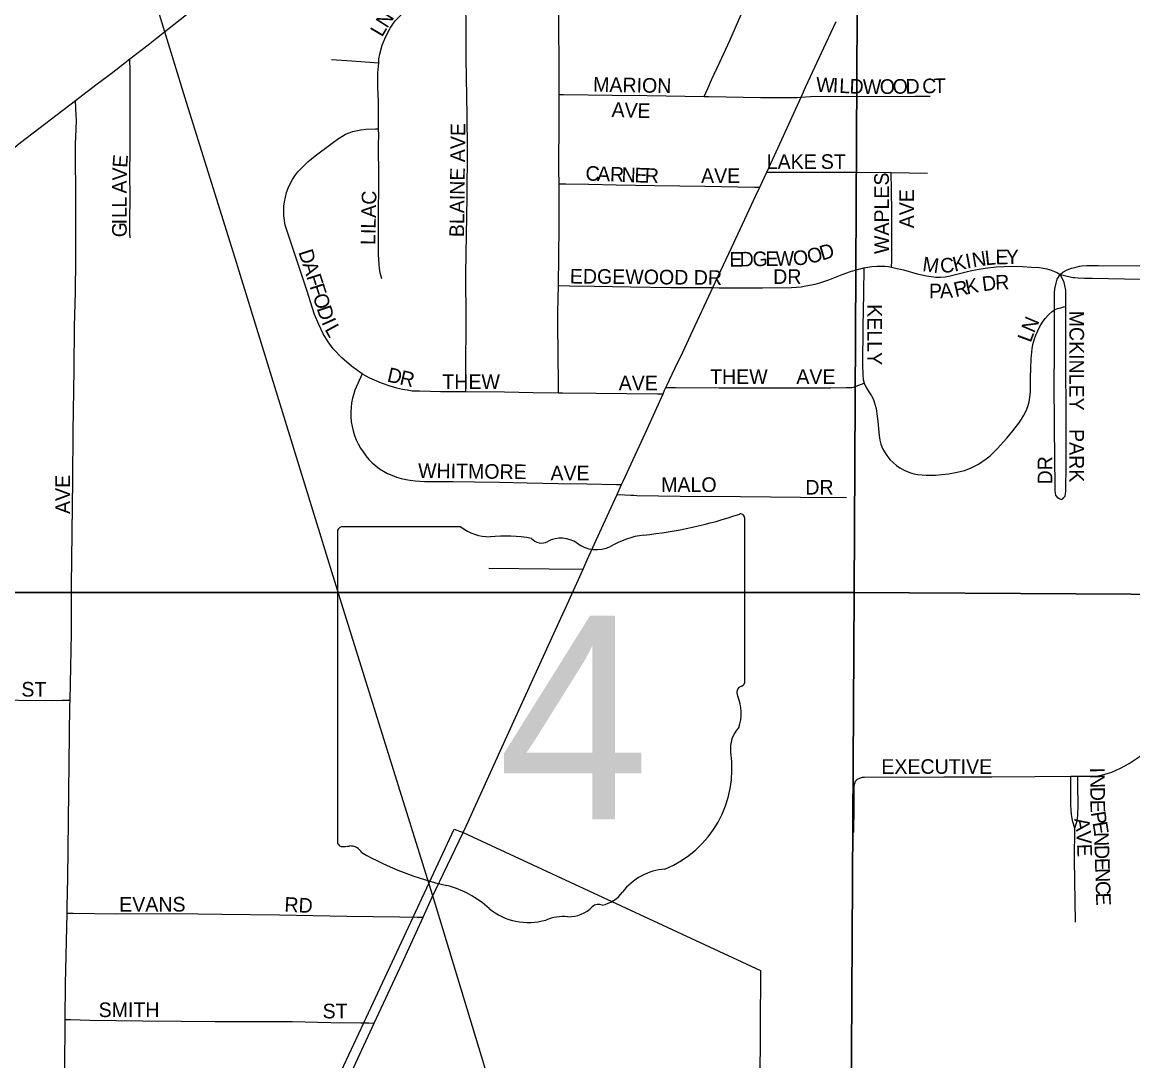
# Model space of a CAD drawing. Extents: x -9.1 to 34, y -3.1 to 22.
# Drawn here: x 4.682 to 5.401, y 18.468 to 19.14 of the extents above; entities that cross this region are included whole.
import ezdxf

# ---------------------------------------------------------------- set-up
doc = ezdxf.new("R2010")
doc.units = 0
for name, color, linetype in [('GM_X_City_Street', 7, 'Continuous'), ('GM_X_City_Street_Text', 7, 'Continuous'), ('GM_X_Corporation', 7, 'Continuous'), ('GM_X_Rail_Line', 7, 'Continuous'), ('GM_X_Section', 7, 'Continuous'), ('GM_X_State_Location', 7, 'Continuous'), ('GM_X_State_Route', 7, 'Continuous'), ('GM_X_State_Shield', 7, 'Continuous')]:
    doc.layers.add(name, color=color, linetype=linetype)

msp = doc.modelspace()

# ---------------------------------------------------------------- linework, layer by layer
at = {"layer": 'GM_X_City_Street'}
for points in [[(4.91297, 19.11392), (4.91314, 19.11648), (4.91366, 19.11945), (4.91532, 19.12531), (4.91758, 19.13096), (4.92048, 19.1363), (4.92217, 19.13882), (4.92372, 19.14106), (4.92573, 19.14333), (4.9315, 19.14874), (4.9371, 19.15333), (4.93817, 19.15402)], [(4.96929, 18.90117), (4.96949, 18.91567), (4.96959, 18.94655), (4.96942, 18.97748), (4.97034, 19.02704), (4.97051, 19.05804), (4.97028, 19.07974), (4.96967, 19.11681), (4.9697, 19.13525), (4.96932, 19.15375)], [(5.02979, 19.09342), (5.02971, 19.10364), (5.0296, 19.1469), (5.02965, 19.15302)], [(5.12373, 19.09213), (5.12599, 19.0973), (5.12848, 19.10298), (5.13376, 19.11422), (5.14028, 19.12825), (5.14764, 19.14525), (5.14855, 19.14822), (5.14927, 19.15143)], [(4.75203, 19.00066), (4.75192, 19.00372), (4.75181, 19.01296), (4.75208, 19.02528), (4.75187, 19.04376), (4.75213, 19.05609), (4.75213, 19.06533), (4.75216, 19.10541), (4.75211, 19.10848), (4.75198, 19.11642)], [(4.88235, 19.11607), (4.89564, 19.11509), (4.91, 19.11412), (4.91297, 19.11392)], [(4.91294, 19.07125), (4.91279, 19.08884), (4.91247, 19.09805), (4.91252, 19.10732), (4.91297, 19.11392)], [(4.71316, 18.70123), (4.71407, 18.74446), (4.71423, 18.77554), (4.71507, 18.8439), (4.71525, 18.87498), (4.71579, 18.91537), (4.71612, 18.94334), (4.71661, 18.96508), (4.71688, 18.98679), (4.71693, 19.02096), (4.71677, 19.06135), (4.7171, 19.07066), (4.71727, 19.07681), (4.71713, 19.07984), (4.71666, 19.08949)], [(5.02971, 19.03553), (5.02961, 19.04447), (5.02991, 19.07835), (5.02979, 19.09342)], [(5.02979, 19.09342), (5.03259, 19.09338), (5.04859, 19.09316), (5.06417, 19.09295), (5.08683, 19.09264), (5.12373, 19.09213)], [(5.12373, 19.09213), (5.12664, 19.09209), (5.16009, 19.09154), (5.17997, 19.09133), (5.18226, 19.0914), (5.18395, 19.09146), (5.18641, 19.09166)], [(5.18641, 19.09166), (5.19246, 19.09206), (5.19491, 19.09222), (5.22894, 19.09206), (5.2602, 19.09228), (5.27002, 19.09225)], [(4.90221, 18.91247), (4.89537, 18.91746), (4.88905, 18.92287), (4.88362, 18.92874), (4.88024, 18.93327), (4.87713, 18.93834), (4.87419, 18.94447), (4.87153, 18.95088), (4.8664, 18.96659), (4.86129, 18.98226), (4.85444, 19.00289), (4.85253, 19.00883), (4.85193, 19.01183), (4.85159, 19.01485), (4.85151, 19.01789), (4.85168, 19.02084), (4.85203, 19.02387), (4.85259, 19.02699), (4.8534, 19.02988), (4.85447, 19.03274), (4.85573, 19.03555), (4.85728, 19.03837), (4.85878, 19.0408), (4.86065, 19.04321), (4.8627, 19.04547), (4.86718, 19.04972), (4.87195, 19.05365), (4.8819, 19.06115), (4.88693, 19.0648), (4.88921, 19.06622), (4.89152, 19.06765), (4.89387, 19.06862), (4.89613, 19.06932), (4.90135, 19.07045), (4.90473, 19.0709), (4.91095, 19.07116), (4.91294, 19.07125)], [(4.91504, 18.97408), (4.914, 18.97798), (4.91348, 18.98085), (4.91326, 18.98351), (4.91292, 18.98976), (4.91287, 19.00522), (4.91298, 19.04547), (4.91291, 19.05475), (4.91292, 19.06093), (4.91297, 19.06712), (4.91294, 19.07125)], [(5.16425, 19.0432), (5.17026, 19.04317), (5.18413, 19.04308), (5.20057, 19.04308), (5.22188, 19.04299), (5.24474, 19.04298)], [(5.24474, 19.04298), (5.25648, 19.04267), (5.26822, 19.04245)], [(5.24498, 18.98153), (5.24511, 18.9858), (5.24511, 18.9979), (5.24511, 19.00599), (5.24511, 19.01746), (5.2449, 19.03159), (5.24474, 19.04298)], [(5.02943, 18.96969), (5.02953, 18.98878), (5.02984, 19.00734), (5.02985, 19.02275), (5.02971, 19.03553)], [(5.02971, 19.03553), (5.03403, 19.03546), (5.0488, 19.03525), (5.06675, 19.035), (5.09165, 19.03448), (5.12419, 19.03395), (5.15621, 19.03343), (5.15972, 19.03336)], [(5.12933, 18.96832), (5.13334, 18.96831), (5.16154, 18.96829), (5.18025, 18.96847), (5.18334, 18.96864), (5.18641, 18.96896), (5.18947, 18.96941), (5.19552, 18.97067), (5.1985, 18.97148), (5.20437, 18.97346), (5.2131, 18.97693), (5.21842, 18.9788), (5.22304, 18.98013), (5.22704, 18.98111)], [(5.22704, 18.98111), (5.2268, 18.96479), (5.22645, 18.94292), (5.22628, 18.91811), (5.22637, 18.91189), (5.22663, 18.9089), (5.22717, 18.90654)], [(5.22704, 18.98111), (5.23219, 18.98191), (5.23549, 18.98218), (5.23789, 18.98227), (5.24065, 18.98218), (5.24296, 18.98191), (5.24498, 18.98153)], [(5.24498, 18.98153), (5.24673, 18.98125), (5.25281, 18.97977), (5.26166, 18.97724), (5.2676, 18.97592), (5.2706, 18.97546), (5.2736, 18.97518), (5.2766, 18.9751), (5.27971, 18.97539), (5.28291, 18.97592), (5.28816, 18.97717), (5.29589, 18.97913), (5.30043, 18.98011), (5.30549, 18.98091), (5.31279, 18.98172), (5.31794, 18.98207), (5.32274, 18.98216), (5.32977, 18.98198), (5.33563, 18.98163), (5.34079, 18.98127), (5.34315, 18.98095), (5.34546, 18.98051), (5.3476, 18.97989), (5.35, 18.97909), (5.35231, 18.97802), (5.35418, 18.97686)], [(5.35418, 18.97686), (5.35595, 18.97832), (5.35861, 18.97977), (5.3615, 18.9809), (5.3636, 18.9814), (5.36521, 18.98185), (5.36672, 18.9822), (5.36814, 18.98238), (5.37134, 18.98256), (5.37881, 18.98274), (5.45205, 18.98239), (5.47362, 18.98231)], [(5.35048, 18.95403), (5.35048, 18.95741), (5.3505, 18.96545), (5.3506, 18.96725), (5.35084, 18.96834), (5.35145, 18.97116), (5.35225, 18.97382), (5.35418, 18.97686)], [(5.3578, 18.95612), (5.35775, 18.9667), (5.35767, 18.96777), (5.35744, 18.96866), (5.35675, 18.97157), (5.35571, 18.97398), (5.35418, 18.97686)], [(5.35418, 18.97686), (5.36058, 18.97527), (5.36227, 18.97491), (5.36366, 18.97481), (5.36576, 18.97467), (5.3698, 18.97452), (5.37507, 18.97438), (5.39588, 18.97412), (5.44625, 18.97379), (5.47099, 18.97364), (5.47359, 18.97362)], [(5.02933, 18.90032), (5.02929, 18.90388), (5.02908, 18.9269), (5.02894, 18.94281), (5.02904, 18.95231), (5.02943, 18.96969)], [(5.02943, 18.96969), (5.03644, 18.96959), (5.05277, 18.96928), (5.07598, 18.96893), (5.10203, 18.96841), (5.12073, 18.96835), (5.12933, 18.96832)], [(5.22717, 18.90654), (5.2286, 18.90362), (5.23037, 18.90078), (5.23206, 18.8982), (5.23305, 18.89624), (5.23375, 18.89446), (5.23438, 18.89233), (5.23492, 18.89011), (5.23554, 18.88673), (5.23599, 18.88343), (5.23625, 18.87979), (5.23652, 18.87659), (5.23687, 18.87268), (5.23741, 18.86956), (5.23812, 18.8669), (5.2391, 18.86423), (5.24035, 18.86192), (5.24186, 18.8597), (5.2439, 18.85712), (5.24621, 18.85481), (5.24808, 18.85321), (5.25039, 18.85161), (5.25351, 18.84983), (5.25716, 18.84832), (5.25955, 18.8477), (5.26195, 18.84725), (5.26747, 18.8469), (5.27342, 18.8469), (5.27752, 18.84734), (5.28178, 18.84788), (5.28747, 18.84886), (5.29228, 18.85002), (5.29619, 18.85144), (5.30125, 18.85402), (5.30632, 18.8574), (5.30888, 18.85949), (5.3133, 18.86387), (5.31955, 18.87079), (5.32354, 18.87557), (5.32728, 18.88056), (5.32901, 18.88314), (5.33061, 18.88581), (5.33204, 18.88857), (5.33319, 18.89144), (5.33405, 18.89441), (5.3346, 18.89746), (5.33489, 18.90055), (5.335, 18.90367), (5.335, 18.90989), (5.33516, 18.91611), (5.33529, 18.92232), (5.336, 18.92863), (5.33654, 18.93148), (5.33734, 18.93459), (5.33847, 18.93756), (5.33962, 18.94044), (5.34102, 18.94323), (5.34263, 18.94589), (5.34449, 18.94837), (5.34664, 18.95075), (5.34887, 18.9528), (5.35048, 18.95403)], [(5.35472, 18.8311), (5.35356, 18.8315), (5.35254, 18.83226), (5.35137, 18.83391), (5.35106, 18.83524), (5.35083, 18.83707), (5.3508, 18.84217), (5.35058, 18.85586), (5.3503, 18.90548), (5.35039, 18.92638), (5.35047, 18.94549), (5.35048, 18.95403)], [(5.35048, 18.95403), (5.35232, 18.95475), (5.35446, 18.95536), (5.35618, 18.95585), (5.3578, 18.95612)], [(5.35472, 18.8311), (5.35575, 18.8315), (5.3566, 18.83248), (5.35731, 18.83339), (5.35767, 18.83494), (5.3579, 18.83632), (5.3579, 18.83718), (5.35806, 18.85361), (5.358, 18.87103), (5.35794, 18.89139), (5.35786, 18.91415), (5.35776, 18.94519), (5.3578, 18.95612)], [(4.90221, 18.91247), (4.89759, 18.90192), (4.89682, 18.89968), (4.89605, 18.89671), (4.89546, 18.89372), (4.8951, 18.8907), (4.89496, 18.88765), (4.895, 18.88458), (4.89526, 18.88154), (4.89572, 18.87852), (4.89641, 18.87556), (4.89729, 18.87265), (4.8984, 18.86983), (4.89976, 18.86711), (4.90128, 18.86449), (4.90299, 18.86192), (4.90475, 18.85942), (4.90668, 18.85711), (4.90882, 18.85491), (4.91109, 18.85289), (4.91352, 18.85107), (4.91609, 18.84944), (4.91879, 18.84803), (4.92159, 18.84682), (4.92446, 18.84572), (4.92748, 18.84483), (4.93184, 18.84386), (4.93655, 18.84324), (4.94259, 18.84288), (4.961, 18.84274), (4.97505, 18.8426), (4.99123, 18.84236), (5.0091, 18.842), (5.02917, 18.8416), (5.0477, 18.8414), (5.06699, 18.84086), (5.07017, 18.84078)], [(4.90221, 18.91247), (4.9071, 18.90998), (4.91457, 18.90678), (4.92026, 18.90474), (4.92462, 18.9035), (4.92844, 18.90259), (4.93141, 18.90211), (4.93462, 18.90162), (4.93936, 18.90147)], [(4.93936, 18.90147), (4.95302, 18.90119), (4.96292, 18.90113), (4.96929, 18.90117)], [(4.96929, 18.90117), (4.99437, 18.90085), (5.01293, 18.9005), (5.02933, 18.90032)], [(5.0989, 18.90367), (5.10516, 18.90363), (5.13335, 18.90347), (5.16509, 18.90341), (5.18536, 18.90337), (5.20559, 18.90344), (5.21568, 18.90357), (5.21746, 18.90357), (5.21933, 18.90375), (5.2211, 18.90419), (5.22386, 18.90526), (5.22717, 18.90654)], [(5.02933, 18.90032), (5.03206, 18.90029), (5.05385, 18.90006), (5.0935, 18.89963), (5.09707, 18.89959)], [(5.06733, 18.83445), (5.07224, 18.83421), (5.07619, 18.83402), (5.07816, 18.83392), (5.08003, 18.83383), (5.10804, 18.83339), (5.14725, 18.83305), (5.18593, 18.83271), (5.2158, 18.83244)], [(4.98424, 18.78675), (5.02342, 18.78624), (5.04537, 18.78615)], [(4.57609, 18.70589), (4.5791, 18.70553), (4.58614, 18.70468), (4.59201, 18.70398), (4.60136, 18.70304), (4.61387, 18.70216), (4.62504, 18.70178), (4.63584, 18.70173), (4.70177, 18.70105), (4.70805, 18.70115), (4.71316, 18.70123)], [(4.71123, 18.56338), (4.71133, 18.56737), (4.71167, 18.586), (4.71229, 18.62328), (4.71309, 18.69787), (4.71316, 18.70123)], [(5.36551, 18.65202), (5.3754, 18.65206), (5.3785, 18.65233), (5.38156, 18.65289), (5.38458, 18.65366), (5.38752, 18.65465), (5.3904, 18.65581), (5.39322, 18.65712), (5.3987, 18.66014), (5.40396, 18.66358), (5.41163, 18.66903), (5.41433, 18.67056), (5.41989, 18.67327), (5.42878, 18.67618), (5.44959, 18.68281), (5.4644, 18.68766), (5.48212, 18.69348), (5.49345, 18.6971)], [(5.22063, 18.61561), (5.22067, 18.63188), (5.22071, 18.64565), (5.22114, 18.64723), (5.22174, 18.64875), (5.22304, 18.65016)], [(5.22304, 18.65016), (5.22483, 18.65102), (5.22618, 18.6514), (5.22748, 18.65144), (5.27873, 18.6517), (5.30993, 18.65168), (5.33768, 18.65189), (5.36114, 18.65199)], [(5.36356, 18.61844), (5.36238, 18.62238), (5.36198, 18.62455), (5.36154, 18.62723), (5.36124, 18.63), (5.36104, 18.63354), (5.36112, 18.64726), (5.36114, 18.65199)], [(5.36114, 18.65199), (5.36551, 18.65202)], [(5.36356, 18.61844), (5.36484, 18.62248), (5.36534, 18.62465), (5.36562, 18.62688), (5.36581, 18.63321), (5.36561, 18.64589), (5.36551, 18.65202)], [(5.36397, 18.55746), (5.36347, 18.59803), (5.36356, 18.61844)], [(4.70999, 18.49453), (4.71016, 18.51765), (4.71123, 18.56338)], [(4.71123, 18.56338), (4.71512, 18.56333), (4.74308, 18.56294), (4.7804, 18.56306), (4.81149, 18.56263), (4.84882, 18.56228), (4.89233, 18.56128), (4.92654, 18.56091), (4.9378, 18.56083), (4.94177, 18.56081)], [(4.70955, 18.4257), (4.70964, 18.43064), (4.70974, 18.46172), (4.70999, 18.49453)], [(4.70999, 18.49453), (4.71352, 18.49444), (4.72598, 18.49413), (4.76001, 18.49372), (4.78521, 18.49337), (4.80706, 18.49322), (4.83828, 18.49313), (4.85701, 18.49308), (4.88197, 18.49264), (4.90132, 18.49239), (4.90662, 18.49226), (4.91007, 18.49218)]]:
    msp.add_lwpolyline(points, dxfattribs=at)
at = {"layer": 'GM_X_Corporation'}
msp.add_lwpolyline([(4.48709, 18.28022), (4.70754, 18.2776), (4.80082, 18.27528), (4.82, 18.31687), (4.83638, 18.35097), (4.87109, 18.42324), (4.90339, 18.49229), (4.93534, 18.5608), (4.96194, 18.61779), (4.96775, 18.61559), (5.16013, 18.52629), (5.15861, 18.26589), (5.2044, 18.26599), (5.22711, 18.26576), (5.2741, 18.26585), (5.53122, 18.26459)], dxfattribs=at)
at = {"layer": 'GM_X_Rail_Line'}
msp.add_lwpolyline([(5.35605, 17.26065), (5.18547, 17.8126), (5.12815, 17.99868), (5.11158, 18.04263), (5.04323, 18.26559), (4.98762, 18.44451), (4.9489, 18.57172), (4.88796, 18.76688), (4.82092, 18.98452), (4.78778, 19.09094), (4.76193, 19.17487)], dxfattribs=at)
at = {"layer": 'GM_X_Section'}
for points in [[(4.2285, 19.77719), (5.226, 19.77229), (5.22068, 18.771), (4.22542, 18.77097)], [(5.226, 19.77229), (6.2379, 19.76083), (6.22532, 18.76489), (5.22068, 18.771)], [(4.22542, 18.77097), (5.22068, 18.771), (5.21493, 17.76405), (4.21254, 17.77165)], [(5.22068, 18.771), (6.22532, 18.76489), (6.22405, 17.76169), (5.21493, 17.76405)]]:
    msp.add_lwpolyline(points, close=True, dxfattribs=at)
at = {"layer": 'GM_X_State_Route'}
for points in [[(4.76383, 19.12561), (4.76922, 19.12978), (4.79575, 19.15075)], [(5.03384, 18.76073), (5.04537, 18.78615), (5.04803, 18.79206), (5.06098, 18.8203), (5.06733, 18.83445), (5.07017, 18.84078), (5.07115, 18.84299), (5.08036, 18.86262), (5.08687, 18.87675), (5.09303, 18.89057), (5.09707, 18.89959), (5.09808, 18.90185), (5.0989, 18.90367), (5.09948, 18.90491), (5.10468, 18.91605), (5.10977, 18.92665), (5.11637, 18.94062), (5.12825, 18.96599), (5.12933, 18.96832), (5.1414, 18.99416), (5.15722, 19.02794), (5.15972, 19.03336), (5.16425, 19.0432), (5.17151, 19.05898), (5.18641, 19.09166), (5.18954, 19.0986), (5.20259, 19.12673), (5.20908, 19.14056)], [(4.61624, 19.01095), (4.66437, 19.04881), (4.68111, 19.06222), (4.71666, 19.08949), (4.72979, 19.09956), (4.73975, 19.10696), (4.75198, 19.11642), (4.76383, 19.12561)], [(4.96775, 18.61559), (4.9696, 18.61966), (4.9937, 18.67303), (5.01163, 18.71226), (5.0309, 18.75426), (5.03384, 18.76073)], [(4.87767, 18.42312), (4.88518, 18.43842), (4.89813, 18.46653), (4.91007, 18.49218), (4.92815, 18.53102), (4.94177, 18.56081), (4.94745, 18.5732), (4.96775, 18.61559)]]:
    msp.add_lwpolyline(points, dxfattribs=at)
at = {"layer": 'GM_X_State_Shield'}
for p, q in [((5.15001, 18.71374), (5.15001, 18.81842)), ((4.88634, 18.81002), (4.88634, 18.6099)), ((4.96615, 18.81346), (4.88894, 18.81346)), ((5.14998, 18.71376), (5.15001, 18.71374))]:
    msp.add_line(p, q, dxfattribs=at)
for centre, radius, start, end in [((5.05609, 19.08629), 0.27962, 275.84447, 288.90645), ((5.14708, 18.81886), 0.00294, 351.86209, 97.738), ((4.88936, 18.81044), 0.00305, 98.1301, 188.1301), ((4.98454, 18.83669), 0.02963, 231.61951, 271.11188), ((4.99437, 18.70111), 0.10636, 80.48669, 94.98827), ((5.09175, 18.75234), 0.05625, 97.34618, 120.76885), ((5.01851, 18.81148), 0.00855, 219.79206, 297.10237), ((5.03106, 18.78835), 0.01777, 54.46668, 119.14113), ((5.054, 18.82008), 0.02138, 233.85621, 294.82819), ((5.14688, 18.71333), 0.00314, 289.60381, 7.73413), ((5.14933, 18.70605), 0.00454, 107.94398, 210.33697), ((5.12043, 18.69282), 0.02727, 340.03296, 23.64957), ((5.16052, 18.66993), 0.01984, 136.8065, 186.92959), ((5.07175, 18.65661), 0.06994, 292.30889, 8.98584), ((4.88939, 18.60946), 0.00308, 171.95839, 258.30661), ((4.88986, 18.62993), 0.02352, 267.33899, 280.60386), ((4.89467, 18.59835), 0.00848, 29.74838, 93.27175), ((5.00173, 18.77815), 0.20192, 240.41292, 257.1985), ((5.10124, 18.55371), 0.0383, 94.40312, 142.57675), ((4.94153, 18.51999), 0.06318, 47.18416, 75.83597), ((5.05271, 18.5905), 0.0226, 282.87319, 323.27711), ((5.00986, 18.59736), 0.04009, 230.70037, 286.29184), ((5.03595, 18.58237), 0.02136, 268.77702, 315.54927), ((5.05527, 18.56299), 0.00601, 65.75173, 132.64842), ((5.03302, 18.52817), 0.03294, 85.69512, 111.20995)]:
    msp.add_arc(centre, radius, start, end, dxfattribs=at)

# ---------------------------------------------------------------- texts
at = {"layer": 'GM_X_City_Street_Text'}
for s, height, rotation, p in [('N', 0.00947, 57.35276, (4.91845, 19.13577)), ('L', 0.00947, 59.48597, (4.91512, 19.13011)), ('MARION', 0.00947, 358.97529, (5.05173, 19.09521)), ('W', 0.00947, 357.17453, (5.19593, 19.0952)), ('I', 0.00947, 357.15724, (5.20675, 19.09467)), ('L', 0.00947, 357.15085, (5.21091, 19.09446)), ('D', 0.00947, 357.18919, (5.21758, 19.09413)), ('W', 0.00947, 359.7945, (5.22637, 19.09371)), ('O', 0.00947, 0.90537, (5.23741, 19.09368)), ('O', 0.00947, 0.92786, (5.24574, 19.09381)), ('D', 0.00947, 0.93858, (5.25407, 19.09394)), ('C', 0.00947, 0.92287, (5.26492, 19.09412)), ('T', 0.00947, 0.93643, (5.27242, 19.09424)), ('A', 0.00947, 357.87971, (5.06364, 19.07892)), ('V', 0.00947, 357.9211, (5.07198, 19.07862)), ('E', 0.00947, 358.29811, (5.08037, 19.07831)), ('BLAINE AVE', 0.00947, 89.30946, (4.96823, 19.00096)), ('E', 0.00947, 85.98055, (4.75012, 19.04575)), ('LAKE', 0.00947, 0.00001, (5.16418, 19.0452)), ('ST', 0.00947, 0.00001, (5.19918, 19.0452)), ('V', 0.00947, 88.57936, (4.74992, 19.03753)), ('C', 0.00947, 357.91126, (5.04675, 19.0377)), ('A', 0.00947, 357.90155, (5.05424, 19.03743)), ('R', 0.00947, 357.91472, (5.06257, 19.03713)), ('N', 0.00947, 357.9211, (5.07007, 19.03685)), ('E', 0.00947, 357.89609, (5.0784, 19.03655)), ('R', 0.00947, 358.24792, (5.08512, 19.0363)), ('AVE', 0.00947, 0.00001, (5.12168, 19.03604)), ('A', 0.00947, 89.95627, (4.74991, 19.02926)), ('WAPLES', 0.00947, 90, (5.24323, 18.99009)), ('LILAC', 0.00947, 88.63187, (4.91073, 18.99586)), ('AVE', 0.00947, 90, (5.25952, 19.00676)), ('L', 0.00947, 89.97066, (4.74991, 19.02009)), ('L', 0.00947, 89.97066, (4.7499, 19.01343)), ('G', 0.00947, 89.97813, (4.7499, 19.00092)), ('I', 0.00947, 89.95628, (4.7499, 19.00925)), ('O', 0.00947, 15.04495, (5.1917, 18.98358)), ('D', 0.00947, 16.56864, (5.20001, 18.98582)), ('D', 0.00947, 288.02028, (4.8609, 18.99138)), ('E', 0.00947, 0.98352, (5.14006, 18.98187)), ('D', 0.00947, 0.98362, (5.14672, 18.98199)), ('G', 0.00947, 0.98362, (5.15505, 18.98213)), ('E', 0.00947, 1.01138, (5.16339, 18.98228)), ('W', 0.00947, 0.9753, (5.17005, 18.98239)), ('O', 0.00947, 4.46346, (5.18151, 18.98261)), ('M', 0.00947, 352.23566, (5.2646, 18.97909)), ('C', 0.00947, 5.38814, (5.27688, 18.97769)), ('K', 0.00947, 13.78316, (5.28583, 18.97864)), ('I', 0.00947, 10.82112, (5.2938, 18.9806)), ('N', 0.00947, 9.28625, (5.29782, 18.98137)), ('L', 0.00947, 6.132, (5.30591, 18.9827)), ('E', 0.00947, 1.03815, (5.31232, 18.9834)), ('Y', 0.00947, 0.13116, (5.31894, 18.98352)), ('A', 0.00947, 288.02106, (4.86348, 18.98346)), ('EDGEWOOD DR', 0.0094697, 359.44379, (5.0367, 18.97104)), ('DR', 0.00947, 0.00001, (5.16835, 18.97076)), ('F', 0.00947, 288.02073, (4.86606, 18.97553)), ('R', 0.00947, 13.01676, (5.28647, 18.9622)), ('K', 0.00947, 11.41707, (5.29371, 18.96387)), ('D', 0.00947, 7.60764, (5.30418, 18.96592)), ('R', 0.00947, 1.77322, (5.31219, 18.967)), ('F', 0.00947, 288.02073, (4.86812, 18.96919)), ('P', 0.00947, 0.10929, (5.26918, 18.96141)), ('A', 0.00947, 3.47872, (5.27646, 18.96144)), ('O', 0.00947, 288.02106, (4.87018, 18.96285)), ('D', 0.00947, 288.03547, (4.87276, 18.95493)), ('KELLY', 0.00947, 270, (5.22926, 18.95759)), ('MCKINLEY', 0.00947, 270, (5.36012, 18.95342)), ('I', 0.00947, 294.23788, (4.87575, 18.94596)), ('L', 0.00947, 298.67549, (4.87782, 18.94144)), ('N', 0.00947, 66.98506, (5.33731, 18.93845)), ('L', 0.00947, 69.54307, (5.33502, 18.93231)), ('D', 0.00947, 347.10369, (4.91794, 18.90765)), ('R', 0.00947, 347.08789, (4.92606, 18.90579)), ('THEW', 0.00947, 0.00001, (5.12751, 18.90604)), ('AVE', 0.00947, 0.00001, (5.18334, 18.90604)), ('THEW', 0.00947, 0.00001, (4.95418, 18.9027)), ('AVE', 0.00947, 0.00001, (5.06834, 18.90187)), ('PARK', 0.00947, 270, (5.36012, 18.87676)), ('DR', 0.00947, 90, (5.34907, 18.84092)), ('WHITMORE', 0.00947, 359.2713, (4.93841, 18.84521)), ('AVE', 0.00947, 0.00001, (5.02418, 18.84354)), ('AVE', 0.00947, 90, (4.71323, 18.82176)), ('MALO', 0.00947, 0.00001, (5.09584, 18.83604)), ('DR', 0.00947, 0.00001, (5.18918, 18.83437)), ('ST', 0.00947, 0.00001, (4.68168, 18.70354)), ('EXECUTIVE', 0.00947, 0.00001, (5.23835, 18.65354)), ('I', 0.00947, 270.69923, (5.37346, 18.65756)), ('N', 0.00947, 270.67764, (5.37351, 18.65339)), ('D', 0.00947, 270.69119, (5.37361, 18.64506)), ('E', 0.00947, 270.68304, (5.37371, 18.63672)), ('P', 0.00947, 279.43041, (5.37393, 18.62849)), ('A', 0.00947, 278.99877, (5.36326, 18.6243)), ('E', 0.00947, 279.33205, (5.37502, 18.62191)), ('V', 0.00947, 273.71813, (5.36454, 18.6163)), ('N', 0.00947, 271.7708, (5.37607, 18.61566)), ('E', 0.00947, 272.35068, (5.36507, 18.60804)), ('D', 0.00947, 271.74896, (5.37633, 18.60734)), ('E', 0.00947, 271.74896, (5.37658, 18.59901)), ('N', 0.00947, 271.76215, (5.37679, 18.59234)), ('C', 0.00947, 271.74896, (5.37704, 18.58401)), ('EVANS', 0.00947, 0.00001, (4.74501, 18.56437)), ('RD', 0.00947, 356.98902, (4.85177, 18.56437)), ('E', 0.00947, 271.76405, (5.37727, 18.57651)), ('SMITH', 0.00947, 0.00001, (4.73168, 18.49604)), ('ST', 0.00947, 0.00001, (4.87668, 18.49521))]:
    msp.add_text(s, height=height, rotation=rotation, dxfattribs=at).set_placement(p)
at = {"layer": 'GM_X_State_Location'}
for s in ['s', 'r']:
    msp.add_text(s, height=0.000189, dxfattribs=at).set_placement((5.0152, 18.69665))
msp.add_text('4', height=0.000189, rotation=0.00001, dxfattribs=at).set_placement((4.98668, 18.68287))
at = {"layer": 'GM_X_State_Shield'}
msp.add_text('4', height=0.13184, dxfattribs=at).set_placement((4.99015, 18.62401))

doc.saveas('drawing.dxf')
